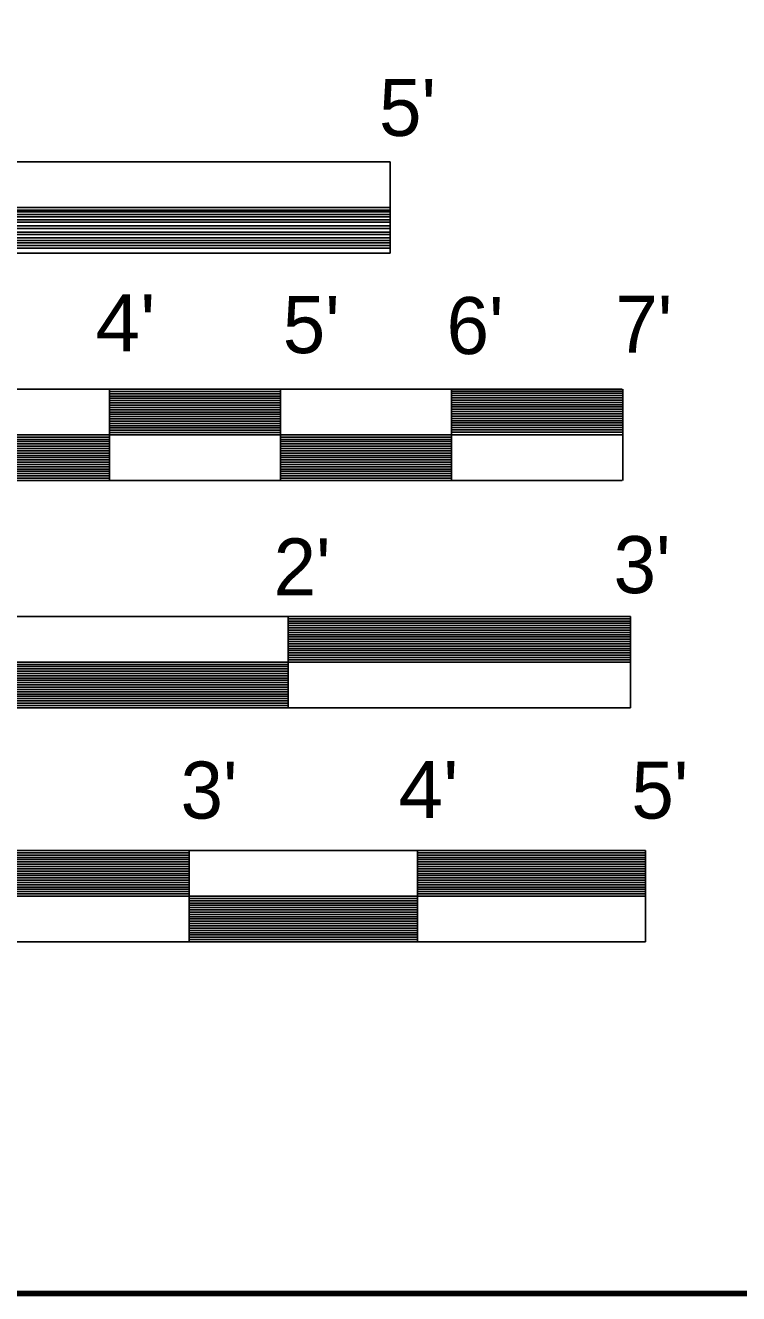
# Model space of a CAD drawing. Extents: x -28.1 to 13.9, y -16.1 to 13.9.
# Drawn here: x 2.736 to 4.299, y -14.627 to -11.848 of the extents above; entities that cross this region are included whole.
import ezdxf
from ezdxf.enums import TextEntityAlignment as Align

# ---------------------------------------------------------------- set-up
doc = ezdxf.new("R2010")
doc.units = 0
doc.header["$LTSCALE"] = 0.05
doc.layers.add('1', color=7, linetype='Continuous', lineweight=13)
doc.layers.add('2', color=7, linetype='Continuous', lineweight=13)

msp = doc.modelspace()

# ---------------------------------------------------------------- linework, layer by layer
at = {"layer": '1', "lineweight": 25}
for p, q in [((1.03496, -12.14731), (3.53496, -12.14731)), ((3.53496, -12.34731), (3.53496, -12.14731)), ((1.03496, -12.24731), (3.53496, -12.24731)), ((2.28496, -12.25331), (3.53496, -12.25331)), ((2.28496, -12.25631), (3.53496, -12.25631)), ((2.28496, -12.26231), (3.53496, -12.26231)), ((2.28496, -12.26731), (3.53496, -12.26731)), ((2.28496, -12.27431), (3.53496, -12.27431)), ((2.28496, -12.27931), (3.53496, -12.27931)), ((2.28496, -12.28731), (3.53496, -12.28731)), ((2.28496, -12.29331), (3.53496, -12.29331)), ((2.28496, -12.30131), (3.53496, -12.30131)), ((2.28496, -12.30631), (3.53496, -12.30631)), ((2.28496, -12.31331), (3.53496, -12.31331)), ((2.28496, -12.31931), (3.53496, -12.31931)), ((2.28496, -12.32431), (3.53496, -12.32431)), ((2.28496, -12.33031), (3.53496, -12.33031)), ((2.28496, -12.33631), (3.53496, -12.33631)), ((1.03496, -12.34731), (3.53496, -12.34731)), ((1.04396, -12.64531), (4.04396, -12.64531)), ((2.91996, -12.84531), (2.91996, -12.64531)), ((3.29496, -12.84531), (3.29496, -12.64531)), ((3.66996, -12.84531), (3.66996, -12.64531)), ((4.04496, -12.84531), (4.04496, -12.64531)), ((2.91996, -12.65031), (3.29496, -12.65031)), ((2.91996, -12.65531), (3.29496, -12.65531)), ((2.91996, -12.66031), (3.29496, -12.66031)), ((2.91996, -12.66531), (3.29496, -12.66531)), ((2.91996, -12.67031), (3.29496, -12.67031)), ((3.66996, -12.64931), (4.04496, -12.64931)), ((3.66996, -12.65431), (4.04496, -12.65431)), ((3.66996, -12.65931), (4.04496, -12.65931)), ((3.66996, -12.66431), (4.04496, -12.66431)), ((3.66996, -12.66931), (4.04496, -12.66931)), ((2.91996, -12.67531), (3.29496, -12.67531)), ((2.91996, -12.68031), (3.29496, -12.68031)), ((2.91996, -12.68531), (3.29496, -12.68531)), ((2.91996, -12.69031), (3.29496, -12.69031)), ((2.91996, -12.69531), (3.29496, -12.69531)), ((2.91996, -12.70031), (3.29496, -12.70031)), ((3.66996, -12.67431), (4.04496, -12.67431)), ((3.66996, -12.67931), (4.04496, -12.67931)), ((3.66996, -12.68431), (4.04496, -12.68431)), ((3.66996, -12.68931), (4.04496, -12.68931)), ((3.66996, -12.69431), (4.04496, -12.69431)), ((3.66996, -12.69931), (4.04496, -12.69931)), ((2.91996, -12.70531), (3.29496, -12.70531)), ((2.91996, -12.71031), (3.29496, -12.71031)), ((2.91996, -12.71531), (3.29496, -12.71531)), ((2.91996, -12.72031), (3.29496, -12.72031)), ((2.91996, -12.72531), (3.29496, -12.72531)), ((3.66996, -12.70431), (4.04496, -12.70431)), ((3.66996, -12.70931), (4.04496, -12.70931)), ((3.66996, -12.71431), (4.04496, -12.71431)), ((3.66996, -12.71931), (4.04496, -12.71931)), ((3.66996, -12.72431), (4.04496, -12.72431)), ((1.04396, -12.74531), (4.04396, -12.74531)), ((2.54496, -12.75031), (2.91996, -12.75031)), ((2.54496, -12.75531), (2.91996, -12.75531)), ((2.91996, -12.73031), (3.29496, -12.73031)), ((2.91996, -12.73531), (3.29496, -12.73531)), ((2.91996, -12.74031), (3.29496, -12.74031)), ((3.29496, -12.75031), (3.66996, -12.75031)), ((3.29496, -12.75531), (3.66996, -12.75531)), ((3.66996, -12.72931), (4.04496, -12.72931)), ((3.66996, -12.73431), (4.04496, -12.73431)), ((3.66996, -12.73931), (4.04496, -12.73931)), ((2.54496, -12.76031), (2.91996, -12.76031)), ((2.54496, -12.76531), (2.91996, -12.76531)), ((2.54496, -12.77031), (2.91996, -12.77031)), ((2.54496, -12.77531), (2.91996, -12.77531)), ((2.54496, -12.78031), (2.91996, -12.78031)), ((3.29496, -12.76031), (3.66996, -12.76031)), ((3.29496, -12.76531), (3.66996, -12.76531)), ((3.29496, -12.77031), (3.66996, -12.77031)), ((3.29496, -12.77531), (3.66996, -12.77531)), ((3.29496, -12.78031), (3.66996, -12.78031)), ((2.54496, -12.78531), (2.91996, -12.78531)), ((2.54496, -12.79031), (2.91996, -12.79031)), ((2.54496, -12.79531), (2.91996, -12.79531)), ((2.54496, -12.80031), (2.91996, -12.80031)), ((2.54496, -12.80531), (2.91996, -12.80531)), ((2.54496, -12.81031), (2.91996, -12.81031)), ((3.29496, -12.78531), (3.66996, -12.78531)), ((3.29496, -12.79031), (3.66996, -12.79031)), ((3.29496, -12.79531), (3.66996, -12.79531)), ((3.29496, -12.80031), (3.66996, -12.80031)), ((3.29496, -12.80531), (3.66996, -12.80531)), ((3.29496, -12.81031), (3.66996, -12.81031)), ((2.54496, -12.81531), (2.91996, -12.81531)), ((2.54496, -12.82031), (2.91996, -12.82031)), ((2.54496, -12.82531), (2.91996, -12.82531)), ((2.54496, -12.83031), (2.91996, -12.83031)), ((2.54496, -12.83531), (2.91996, -12.83531)), ((3.29496, -12.81531), (3.66996, -12.81531)), ((3.29496, -12.82031), (3.66996, -12.82031)), ((3.29496, -12.82531), (3.66996, -12.82531)), ((3.29496, -12.83031), (3.66996, -12.83031)), ((3.29496, -12.83531), (3.66996, -12.83531)), ((1.04396, -12.84531), (4.04396, -12.84531)), ((2.54496, -12.84031), (2.91996, -12.84031)), ((3.29496, -12.84031), (3.66996, -12.84031)), ((1.09496, -13.65631), (4.09496, -13.65631)), ((2.59496, -13.66131), (3.09496, -13.66131)), ((2.59496, -13.66631), (3.09496, -13.66631)), ((2.59496, -13.67131), (3.09496, -13.67131)), ((3.09496, -13.85631), (3.09496, -13.65631)), ((3.59496, -13.85631), (3.59496, -13.65631)), ((3.59496, -13.66131), (4.09496, -13.66131)), ((3.59496, -13.66631), (4.09496, -13.66631)), ((3.59496, -13.67131), (4.09496, -13.67131)), ((4.09496, -13.85631), (4.09496, -13.65631)), ((2.59496, -13.67631), (3.09496, -13.67631)), ((2.59496, -13.68131), (3.09496, -13.68131)), ((2.59496, -13.68631), (3.09496, -13.68631)), ((2.59496, -13.69131), (3.09496, -13.69131)), ((2.59496, -13.69631), (3.09496, -13.69631)), ((2.59496, -13.70131), (3.09496, -13.70131)), ((3.59496, -13.67631), (4.09496, -13.67631)), ((3.59496, -13.68131), (4.09496, -13.68131)), ((3.59496, -13.68631), (4.09496, -13.68631)), ((3.59496, -13.69131), (4.09496, -13.69131)), ((3.59496, -13.69631), (4.09496, -13.69631)), ((3.59496, -13.70131), (4.09496, -13.70131)), ((2.59496, -13.70631), (3.09496, -13.70631)), ((2.59496, -13.71131), (3.09496, -13.71131)), ((2.59496, -13.71631), (3.09496, -13.71631)), ((2.59496, -13.72131), (3.09496, -13.72131)), ((2.59496, -13.72631), (3.09496, -13.72631)), ((3.59496, -13.70631), (4.09496, -13.70631)), ((3.59496, -13.71131), (4.09496, -13.71131)), ((3.59496, -13.71631), (4.09496, -13.71631)), ((3.59496, -13.72131), (4.09496, -13.72131)), ((3.59496, -13.72631), (4.09496, -13.72631)), ((1.09496, -13.75631), (4.09496, -13.75631)), ((2.59496, -13.73131), (3.09496, -13.73131)), ((2.59496, -13.73631), (3.09496, -13.73631)), ((2.59496, -13.74131), (3.09496, -13.74131)), ((2.59496, -13.74631), (3.09496, -13.74631)), ((2.59496, -13.75131), (3.09496, -13.75131)), ((3.59496, -13.73131), (4.09496, -13.73131)), ((3.59496, -13.73631), (4.09496, -13.73631)), ((3.59496, -13.74131), (4.09496, -13.74131)), ((3.59496, -13.74631), (4.09496, -13.74631)), ((3.59496, -13.75131), (4.09496, -13.75131)), ((3.09496, -13.76131), (3.59496, -13.76131)), ((3.09496, -13.76631), (3.59496, -13.76631)), ((3.09496, -13.77131), (3.59496, -13.77131)), ((3.09496, -13.77631), (3.59496, -13.77631)), ((3.09496, -13.78131), (3.59496, -13.78131)), ((3.09496, -13.78631), (3.59496, -13.78631)), ((3.09496, -13.79131), (3.59496, -13.79131)), ((3.09496, -13.79631), (3.59496, -13.79631)), ((3.09496, -13.80131), (3.59496, -13.80131)), ((3.09496, -13.80631), (3.59496, -13.80631)), ((3.09496, -13.81131), (3.59496, -13.81131)), ((3.09496, -13.81631), (3.59496, -13.81631)), ((3.09496, -13.82131), (3.59496, -13.82131)), ((3.09496, -13.82631), (3.59496, -13.82631)), ((3.09496, -13.83131), (3.59496, -13.83131)), ((3.09496, -13.83631), (3.59496, -13.83631)), ((1.09496, -13.85631), (4.09496, -13.85631)), ((3.09496, -13.84131), (3.59496, -13.84131)), ((3.09496, -13.84631), (3.59496, -13.84631)), ((3.09496, -13.85131), (3.59496, -13.85131))]:
    msp.add_line(p, q, dxfattribs=at)
at = {"layer": '1', "lineweight": 90}
msp.add_lwpolyline([(-25.64304, 12.37269), (12.35696, 12.37269), (12.35696, -14.62731), (-25.64304, -14.62731)], close=True, dxfattribs=at)
at = {"layer": '2', "lineweight": 25}
for p, q in [((1.06196, -13.14331), (4.06196, -13.14331)), ((3.31196, -13.34331), (3.31196, -13.14331)), ((4.06196, -13.34331), (4.06196, -13.14331)), ((3.31196, -13.14831), (4.06196, -13.14831)), ((3.31196, -13.15331), (4.06196, -13.15331)), ((3.31196, -13.15831), (4.06196, -13.15831)), ((3.31196, -13.16331), (4.06196, -13.16331)), ((3.31196, -13.16831), (4.06196, -13.16831)), ((3.31196, -13.17331), (4.06196, -13.17331)), ((3.31196, -13.17831), (4.06196, -13.17831)), ((3.31196, -13.18331), (4.06196, -13.18331)), ((3.31196, -13.18831), (4.06196, -13.18831)), ((3.31196, -13.19331), (4.06196, -13.19331)), ((3.31196, -13.19831), (4.06196, -13.19831)), ((3.31196, -13.20331), (4.06196, -13.20331)), ((3.31196, -13.20831), (4.06196, -13.20831)), ((3.31196, -13.21331), (4.06196, -13.21331)), ((3.31196, -13.21831), (4.06196, -13.21831)), ((3.31196, -13.22331), (4.06196, -13.22331)), ((3.31196, -13.22831), (4.06196, -13.22831)), ((1.06196, -13.24331), (4.06196, -13.24331)), ((2.56196, -13.24831), (3.31196, -13.24831)), ((2.56196, -13.25331), (3.31196, -13.25331)), ((3.31196, -13.23331), (4.06196, -13.23331)), ((3.31196, -13.23831), (4.06196, -13.23831)), ((2.56196, -13.25831), (3.31196, -13.25831)), ((2.56196, -13.26331), (3.31196, -13.26331)), ((2.56196, -13.26831), (3.31196, -13.26831)), ((2.56196, -13.27331), (3.31196, -13.27331)), ((2.56196, -13.27831), (3.31196, -13.27831)), ((2.56196, -13.28331), (3.31196, -13.28331)), ((2.56196, -13.28831), (3.31196, -13.28831)), ((2.56196, -13.29331), (3.31196, -13.29331)), ((2.56196, -13.29831), (3.31196, -13.29831)), ((2.56196, -13.30331), (3.31196, -13.30331)), ((2.56196, -13.30831), (3.31196, -13.30831)), ((2.56196, -13.31331), (3.31196, -13.31331)), ((2.56196, -13.31831), (3.31196, -13.31831)), ((2.56196, -13.32331), (3.31196, -13.32331)), ((2.56196, -13.32831), (3.31196, -13.32831)), ((2.56196, -13.33331), (3.31196, -13.33331)), ((2.56196, -13.33831), (3.31196, -13.33831)), ((1.06196, -13.34331), (4.06196, -13.34331))]:
    msp.add_line(p, q, dxfattribs=at)

# ---------------------------------------------------------------- texts
at = {"layer": '1'}
for s, p in [("5'", (3.57331, -12.09031)), ("5'", (3.36231, -12.56631)), ("6'", (3.72131, -12.56831)), ("7'", (4.0913, -12.56531)), ("5'", (4.12631, -13.58631))]:
    msp.add_text(s, height=0.125, dxfattribs=at).set_placement(p, align=Align.CENTER)
at = {"layer": '1', "width": 1.05}
for p in [(2.9553, -12.56231), (3.6193, -13.58531)]:
    msp.add_text("4'", height=0.125, dxfattribs=at).set_placement(p, align=Align.CENTER)
at = {"layer": '2'}
for s, p in [("2'", (3.34231, -13.09731)), ("3'", (4.08731, -13.09231)), ("3'", (3.13831, -13.58631))]:
    msp.add_text(s, height=0.125, dxfattribs=at).set_placement(p, align=Align.CENTER)

doc.saveas('drawing.dxf')
